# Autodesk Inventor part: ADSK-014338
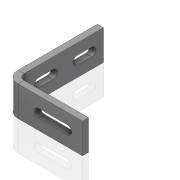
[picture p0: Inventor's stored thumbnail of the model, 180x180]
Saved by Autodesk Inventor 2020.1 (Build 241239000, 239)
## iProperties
Created: 2019-10
Part Number: ADSK-014338
Material: 1.0312 DC05
Document SubType Name: Blech
Designer: lutzd
Mass: 14.1529 g
Surface Area: 80.3382 cm^2
Volume: 14.1529 cm^3
Density: 1 g/cm^3
Sheet Metal Rule: Stahlblech 1.0312 - DC05 -   5.0 mm
Appearance: Stahl
Flat Pattern Width: 2.5 cm
Flat Pattern Length: 13.081 cm
Flat Pattern Area: 32.7024 cm^2
Sheet Metal Width: 25,000 mm
Sheet Metal Length: 130,810 mm
Sheet Metal Area: 3270,243 mm^2
VLDS_Profile: Default Part
VLDS_TimeStamp: 2016-07-29
VLDS_FailCnt: 0
VLDS_AcceptCnt: 0
Dimensions: 76x25x63,5 mm
Semi finished: Stahlblech 1.0312 - DC05 -   5.0 mm
Mass: 0,014 kg
DocNumber: ADSK-014338
Folder: 01 - Themengebiete\Simplification\01 - Packaging machine\
VDS_Category: 3D Komponenten
VDS_NumSchm: Autodesk
G_L: 25x130,8 mm
Thickness: 5,000 mm
VLT_Material: 1.0312 DC05
Title: angle
Author: lutzd
Revision Number: -
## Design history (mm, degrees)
node "Konturlasche1"
  sketch "Skizze1"
    geometry: L1 (0, 0)-(0, 76); L2 (0, 0)-(63.5, 0)
    constraints: 4 end point, 1 horizontal, 1 vertical
    dimensions: "d0" = 76 distance of L1.start L1.end; "d1" = 63.5 distance of L1.start L2.end
sketch "Skizze2"
  geometry: L1 (12.5, -22)-(12.5, -10); L2 (16, -22)-(16, -10); L3 (9, -10)-(9, -22); L4 (12.5, -54)-(12.5, -42); L5 (16, -54)-(16, -42); L6 (9, -42)-(9, -54); L7 (0, 0)-(25, 0) reference; A1 r 3.5 centre (12.5, -22) between (9, -22) and (16, -22); A2 r 3.5 centre (12.5, -10) between (16, -10) and (9, -10); A3 r 3.5 centre (12.5, -54) between (9, -54) and (16, -54); A4 r 3.5 centre (12.5, -42) between (16, -42) and (9, -42); 4 further points
  constraints: 16 end point, 8 point on circle, 8 tangent, 4 centre point, 3 midpoint, 2 parallel, 2 vertical, 1 collinear, 1 vertical alignment
  dimensions: "d13" = 6 distance of point (12.5, -16) L1.end; "d14" = 7 diameter of A2; "d15" = 6 distance of point (12.5, -48) L4.end; "d16" = 7 diameter of A4; "d17" = 10 distance from line of L7 L1.end; "d19" = 32 distance of L4.start L1.start
feature "Ausklinkung1" sketch "Skizze2" dims "d20" = 5 (= Stärke), "d21" = 0
sketch "Skizze3"
  geometry: L1 (-36.5, 12.5)-(-12.5, 12.5); L2 (-36.5, 9)-(-12.5, 9); L3 (-12.5, 16)-(-36.5, 16); L4 (0, 25)-(0, 0) reference; A1 r 3.5 centre (-36.5, 12.5) between (-36.5, 16) and (-36.5, 9); A2 r 3.5 centre (-12.5, 12.5) between (-12.5, 9) and (-12.5, 16); 3 further points
  constraints: 8 end point, 4 point on circle, 4 tangent, 2 centre point, 2 midpoint, 1 horizontal, 1 horizontal alignment, 1 parallel
  dimensions: "d22" = 12 distance of point (-24.5, 12.5) L1.end; "d23" = 7 diameter of A2; "d24" = 12.5 distance from line of L4 L1.end
feature "Ausklinkung2" sketch "Skizze3" dims "d25" = 5 (= Stärke), "d26" = 0
node "Volumenkörper1"
feature "Grobblech1" dims "d2" = 5 (= Stärke), "d3" = 5 (= BreiteBiegungsfreistellung), "d4" = 2.5 (= TiefeBiegungsfreistellung), "d5" = 10 (= MinimalRest), "d6" = 5 (= Übergangsradius), "d7" = 25, "d8" = 5 (= Biegeradius), "d9" = 5, "d10" = 20 (= GrößeEckenfreistellung), "d11" = 5 (= Abstandsgröße), "d12" = 5 (= JacobiRadiusGröße), "AbstandVerbindung" = 0.01
feature "Biegung1" dims "d2" = 5 (= Stärke), "d3" = 5 (= BreiteBiegungsfreistellung), "d4" = 2.5 (= TiefeBiegungsfreistellung), "d5" = 10 (= MinimalRest), "d6" = 5 (= Übergangsradius), "d8" = 5 (= Biegeradius), "d9" = 5, "AbstandVerbindung" = 0.01
feature "Ecke1" dims "d9" = 5, "d10" = 20 (= GrößeEckenfreistellung), "d11" = 5 (= Abstandsgröße), "d12" = 5 (= JacobiRadiusGröße)
feature "Definition1"
other parameters: "Stärke" = 5 (derived), "KFaktor" = 4.4, "Biegeradius" = 5 (= Stärke), "BreiteBiegungsfreistellung" = 5 (= Stärke), "TiefeBiegungsfreistellung" = 2.5 (= 0.5 x Stärke), "Übergangsradius" = 5 (= Biegeradius), "JacobiRadiusGröße" = 5 (= Biegeradius), "Abstandsgröße" = 5 (= Stärke), "Abstandsgröße" = 5, "Biegeradius" = 5, "BreiteBiegungsfreistellung" = 5, "JacobiRadiusGröße" = 5, "Stärke" = 5, "TiefeBiegungsfreistellung" = 2.5, "Übergangsradius" = 5
